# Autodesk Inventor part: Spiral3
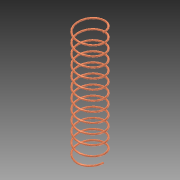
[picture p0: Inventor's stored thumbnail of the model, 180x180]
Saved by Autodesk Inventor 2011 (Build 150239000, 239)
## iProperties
Created: 2014-02
Part Number: Spiral3
Document SubType Name: Modeling
Designer: Evgeny
Density: 1 g/cm^3
Author: Evgeny
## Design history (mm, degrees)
sketch "Эскиз2"
  geometry: L1 (0, 0)-(0, 24); C1 r 1.5 at (-24.955, 0)
  constraints: 2 end point, 1 centre point, 1 vertical
  dimensions: "d19" = 3 diameter of C1; "d20" = 24.955 distance from line of C1.centre L1
feature "Пружина2" sketch "Эскиз2" pitch "d21" = 18.2; turns "d23" = 11.74; dims "d22" = 10, "d24" = 0, angle "d25" = 1 deg, angle "d26" = 90 deg, "d27" = 1 deg, "d28" = 0.27925
node "Твердое тело2"
